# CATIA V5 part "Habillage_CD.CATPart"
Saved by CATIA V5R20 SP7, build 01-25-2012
Part number: Habillage_CD
Bounding box of the stored display mesh (mm): x -3.9 to 4.6, y -41.704 to -18.012, z 48.139 to 61.925
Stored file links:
  F:\IAO\Catia\Habillage_CD.CATPart
  F:\IAO\Catia\asandre.CATProduct
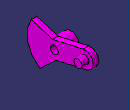
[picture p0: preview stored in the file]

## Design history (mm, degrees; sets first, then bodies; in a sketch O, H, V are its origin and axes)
Set1
  Plane1 "Plan.2,1": linked copy from another document
  Point1 "C": linked copy from another document
  Point2 "D": linked copy from another document
  Point3 "C'": linked copy from another document
Body1 (main body)
  Sketch1 "Bielle_CD" on Plane1, origin (2.1, 0, 0), H (0, 1, 0), V (0, 0, 1)
    construction line L1 (-32, 56.5) -> (-21, 59)
    point P1 (-32, 56.5)
    point P2 (-21, 59)
    line L2 (-32.6649, 59.4254) -> (-21.6649, 61.9254)
    line L3 (-20.3351, 56.0746) -> (-31.3351, 53.5746)
    arc A1 centre (-21, 59) radius 3 from (-21.6649, 61.9254) to (-20.3351, 56.0746) cw
    point P3 (-32.6649, 59.4254)
    point P6 (-31.3351, 53.5746)
    reference projected point E1 (-32, 56.5) from Point1
    reference projected point E2 (-21, 59) from Point2
    circle A2 centre (-32, 56.5) radius 1.5
    point P7 (-32, 56.5)
    reference projected point E3 (-32, 56.5) from Point1
    point P8 (-32.6649, 59.4254)
    line L4 (-32.6649, 59.4254) -> (-40.3073, 61.7905)
    point P9 (-40.3073, 61.7905)
    point P10 (-37.2046, 48.1386)
    point P11 (-31.3351, 53.5746)
    line L5 (-31.3351, 53.5746) -> (-37.2046, 48.1386)
    arc A3 centre (-32, 56.5) radius 9.8489 from (-40.3073, 61.7905) to (-37.2046, 48.1386) ccw
    point P12 (-32, 56.5)
    point P13 (-41.6039, 54.3173)
    reference projected point E4 (-32, 56.5) from Point3
    distance L1 L2 = 3
    radius A2 = 1.5
    length L4 = 8
    angle L2 L4 = 150
    tangency: A1 L2, A1 L3
    coincidence: P1 E1, P2 E2, P7 E3, P3 L2, A3 P13, P13 L1, E4 P12, P3 L4, P6 L5, P3 P8, P11 P6
    symmetry: P9 P10 L1, P8 P11 L1, L4 L5 L1
    parallelism: L3 L2
  Pad1 "Bielle_CD": profile Sketch1, direction (-1, 0, 0), length 2
  Sketch2 "Pivot.D" on Plane1, origin (2.1, 0, 0), H (0, 1, 0), V (0, 0, 1)
    circle A1 centre (-21, 59) radius 1.5
    point P1 (-21, 59)
    reference projected point E1 (-21, 59) from Point2
    radius A1 = 1.5
    coincidence: P1 E1
  Pad2 "Pivot.D": profile Sketch2, direction (1, 0, 0), length 2.5
  Sketch3 "lien.CD_bati" on Plane1, origin (2.1, 0, 0), H (0, 1, 0), V (0, 0, 1)
    circle A1 centre (-32, 56.5) radius 3
    point P1 (-32, 56.5)
    reference projected point E1 (-32, 56.5) from Point1
    circle A2 centre (-32, 56.5) radius 1.5
    point P2 (-32, 56.5)
    reference projected point E2 (-32, 56.5) from Point1
    radius A1 = 3
    radius A2 = 1.5
    coincidence: P1 E1, P2 E2
  Pad3 "Lien.CD_bati": profile Sketch3, direction (-1, 0, 0), length 6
